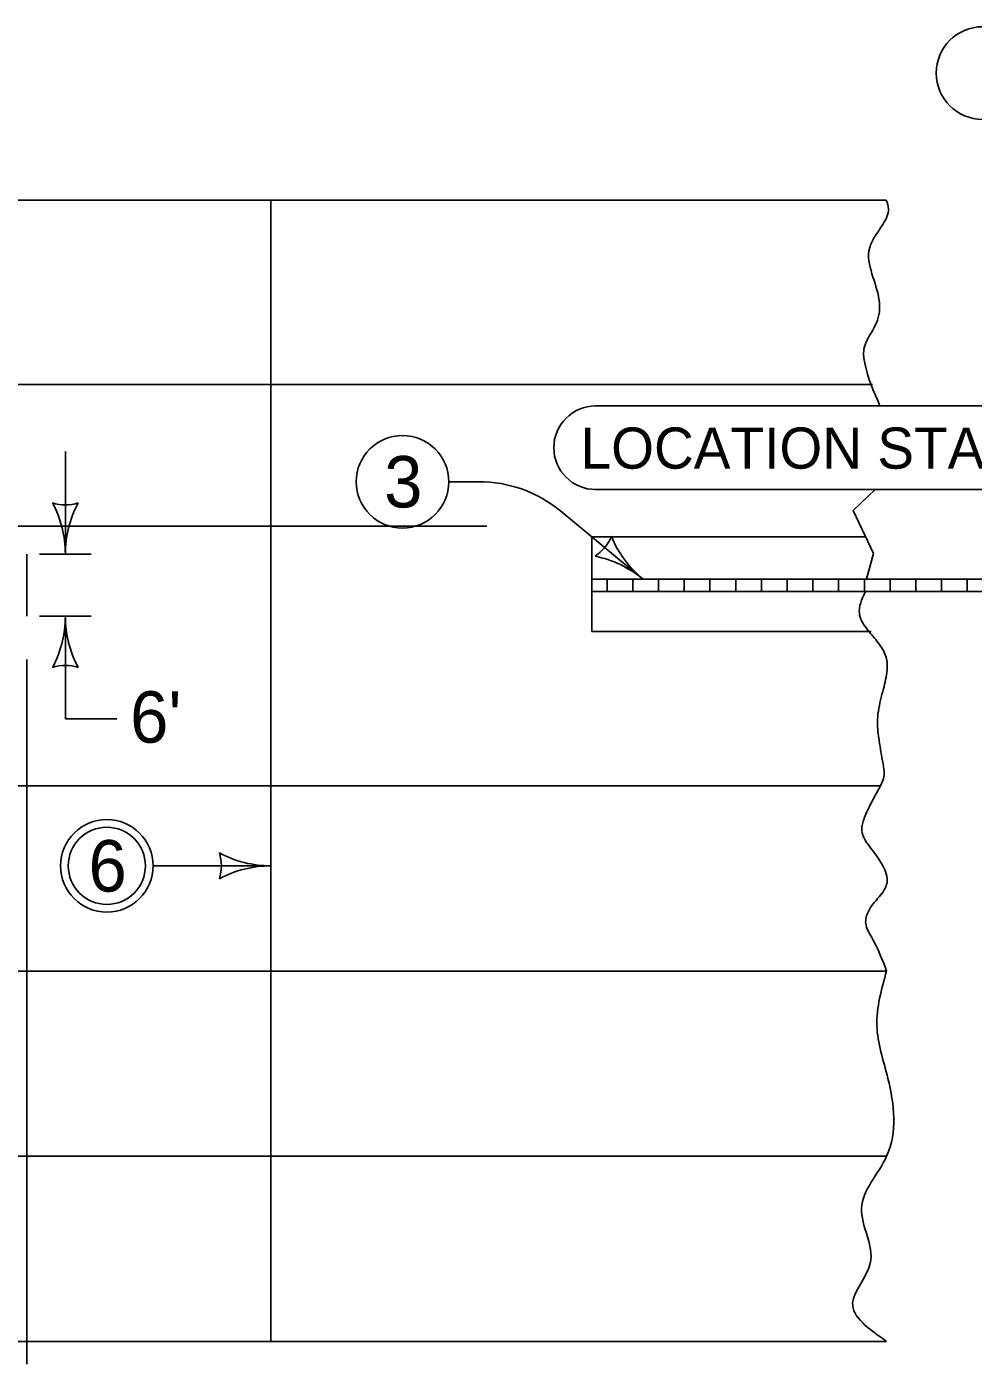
# Model space of a CAD drawing. Extents: x -2135039 to -2131695, y -2139150 to -2136566.
# Drawn here: x -2133246 to -2132878, y -2138511 to -2137991 of the extents above; entities that cross this region are included whole.
import ezdxf

# ---------------------------------------------------------------- set-up
doc = ezdxf.new("R2010")
doc.units = 0
for name, color, linetype in [('dsnStdDimension', 7, 'Continuous'), ('dsnStdLabel', 7, 'Continuous'), ('dsnStdLineDrawingWt4', 7, 'Continuous'), ('dsnStdShading', 7, 'Continuous'), ('Level 10', 7, 'Continuous'), ('Level 2', 7, 'Continuous'), ('Level 3', 7, 'Continuous'), ('Level 7', 7, 'Continuous')]:
    doc.layers.add(name, color=color, linetype=linetype)

msp = doc.modelspace()

# ---------------------------------------------------------------- linework, layer by layer
at = {"layer": 'dsnStdDimension'}
for p, q in [((-2133230.58, -2138196.5), (-2133230.58, -2138156.5)), ((-2133081.57, -2138168.28), (-2133069.91, -2138168.28)), ((-2133038.06, -2138179.74), (-2133006.16, -2138206.1)), ((-2133230.58, -2138260.5), (-2133230.58, -2138220.5)), ((-2133245.58, -2138237.36), (-2133245.58, -2138511.38)), ((-2133230.58, -2138260.5), (-2133210.58, -2138260.5)), ((-2133196.46, -2138317.61), (-2133150.73, -2138317.61))]:
    msp.add_line(p, q, dxfattribs=at)
for centre, radius, start, end in [((-2133069.91, -2138218.28), 50, 50.4322, 90), ((-2133230.58, -2138160.86), 16.42, 252.2666, 287.7333), ((-2133273.08, -2138196.5), 42.5, 0, 28.0725), ((-2133188.08, -2138196.5), 42.5, 151.9275, 180), ((-2133033.63, -2138183.4), 16.42, 302.6988, 338.1655), ((-2132979.09, -2138173.33), 42.5, 202.3597, 230.4322), ((-2133033.23, -2138238.86), 42.5, 50.4322, 78.5047), ((-2133273.08, -2138220.5), 42.5, 331.9275, 0), ((-2133188.08, -2138220.5), 42.5, 180, 208.0725), ((-2133230.58, -2138256.13), 16.42, 72.2666, 107.7334), ((-2133186.37, -2138317.61), 16.42, 342.2666, 17.7333), ((-2133150.73, -2138275.11), 42.5, 241.9275, 270), ((-2133150.73, -2138360.11), 42.5, 90, 118.0725)]:
    msp.add_arc(centre, radius, start, end, dxfattribs=at)
at = {"layer": 'dsnStdLabel'}
for p, q in [((-2132817.04, -2138138.81), (-2133024.52, -2138138.81)), ((-2132817.04, -2138171.31), (-2133024.65, -2138171.31))]:
    msp.add_line(p, q, dxfattribs=at)
msp.add_arc((-2133024.52, -2138155.06), 16.25, 90, 270, dxfattribs=at)
at = {"layer": 'dsnStdLineDrawingWt4'}
for p, q in [((-2134688.01, -2138058.83), (-2133150.73, -2138058.83)), ((-2133150.73, -2138058.83), (-2133150.73, -2138130.5)), ((-2133150.73, -2138058.83), (-2132911.61, -2138058.83)), ((-2133626.99, -2138130.5), (-2132916.93, -2138130.5)), ((-2133150.73, -2138130.5), (-2133150.73, -2138358.5)), ((-2132924.41, -2138179.48), (-2132915.84, -2138171.26)), ((-2132916.57, -2138196.23), (-2132924.41, -2138179.48)), ((-2133025.97, -2138189.71), (-2133025.97, -2138226.5)), ((-2133025.97, -2138189.71), (-2132919.44, -2138189.71)), ((-2133245.58, -2138196.5), (-2133245.58, -2138208.5)), ((-2133240.58, -2138196.5), (-2133220.58, -2138196.5)), ((-2132916.57, -2138196.21), (-2132919.29, -2138206.1)), ((-2133245.58, -2138220.5), (-2133245.58, -2138208.5)), ((-2133025.8, -2138206.1), (-2132697.81, -2138206.1)), ((-2133020.1, -2138210.9), (-2133020.1, -2138206.1)), ((-2133010.1, -2138210.9), (-2133010.1, -2138206.1)), ((-2133000.1, -2138210.9), (-2133000.1, -2138206.1)), ((-2132990.1, -2138210.9), (-2132990.1, -2138206.1)), ((-2132980.1, -2138210.9), (-2132980.1, -2138206.1)), ((-2132970.1, -2138210.9), (-2132970.1, -2138206.1)), ((-2132960.1, -2138210.9), (-2132960.1, -2138206.1)), ((-2132950.1, -2138210.9), (-2132950.1, -2138206.1)), ((-2132940.1, -2138210.9), (-2132940.1, -2138206.1)), ((-2132930.1, -2138210.9), (-2132930.1, -2138206.1)), ((-2132920.1, -2138210.9), (-2132920.1, -2138206.1)), ((-2132910.1, -2138210.9), (-2132910.1, -2138206.1)), ((-2132900.1, -2138210.9), (-2132900.1, -2138206.1)), ((-2132890.1, -2138210.9), (-2132890.1, -2138206.1)), ((-2132880.1, -2138210.9), (-2132880.1, -2138206.1)), ((-2133025.8, -2138210.9), (-2132699.53, -2138210.9)), ((-2133240.58, -2138220.5), (-2133220.58, -2138220.5)), ((-2133025.97, -2138226.5), (-2132917.42, -2138226.5)), ((-2133626.99, -2138286.5), (-2132913.93, -2138286.5)), ((-2134688.98, -2138358.5), (-2133150.73, -2138358.5)), ((-2133150.73, -2138358.5), (-2133150.73, -2138502.5)), ((-2133150.73, -2138358.5), (-2132911.43, -2138358.5)), ((-2134750.5, -2138502.5), (-2132911.43, -2138502.5))]:
    msp.add_line(p, q, dxfattribs=at)
for points in [[(-2132914.03, -2138138.76), (-2132919.94, -2138122.2), (-2132920.28, -2138116.92), (-2132917.92, -2138111.21), (-2132914.44, -2138103.44), (-2132914.25, -2138098.58), (-2132916.74, -2138088.73), (-2132918.31, -2138078.63), (-2132912.93, -2138068.22), (-2132910.7, -2138062.24), (-2132911.61, -2138058.83)], [(-2132911.43, -2138358.5), (-2132917.23, -2138345.45), (-2132919.56, -2138339.99), (-2132918.54, -2138335.31), (-2132914.37, -2138329.68), (-2132911.27, -2138324.04), (-2132912.91, -2138317.6), (-2132917.35, -2138311.07), (-2132921.11, -2138303.77), (-2132920.14, -2138299.02), (-2132914.6, -2138287.94), (-2132912.42, -2138282.19), (-2132912.83, -2138277.9), (-2132914.35, -2138268.88), (-2132914.98, -2138261.83), (-2132914.66, -2138257.54), (-2132912.68, -2138248.78), (-2132911.29, -2138241.52), (-2132911.43, -2138237.17), (-2132913.81, -2138232.16), (-2132917.66, -2138227.23), (-2132921.46, -2138221.65), (-2132922.08, -2138218.44), (-2132921.16, -2138214.35), (-2132919.59, -2138210.9)], [(-2132911.44, -2138358.48), (-2132915.23, -2138379.71), (-2132910.95, -2138400.25), (-2132911.43, -2138430.5), (-2132921.22, -2138450.76), (-2132917.8, -2138472.17), (-2132924.65, -2138487.58), (-2132911.43, -2138502.5)]]:
    msp.add_spline(points, degree=3, dxfattribs=at)
at = {"layer": 'dsnStdShading'}
for p, q in [((-2133150.73, -2138058.83), (-2134688.01, -2138058.83)), ((-2132911.61, -2138058.83), (-2133150.73, -2138058.83)), ((-2133024.52, -2138138.81), (-2132914.03, -2138138.81)), ((-2132915.89, -2138171.31), (-2133024.52, -2138171.31)), ((-2132924.41, -2138179.48), (-2132915.89, -2138171.31)), ((-2132916.57, -2138196.21), (-2132924.41, -2138179.48)), ((-2133020.1, -2138210.9), (-2133020.1, -2138206.1)), ((-2134688.98, -2138358.5), (-2133150.73, -2138358.5)), ((-2133150.73, -2138358.5), (-2132911.43, -2138358.5))]:
    msp.add_line(p, q, dxfattribs=at)
for points in [[(-2132914.03, -2138138.81), (-2132914.03, -2138138.76)], [(-2133020.1, -2138206.1), (-2133010.1, -2138206.1), (-2133000.1, -2138206.1), (-2132990.1, -2138206.1), (-2132980.1, -2138206.1), (-2132970.1, -2138206.1), (-2132960.1, -2138206.1), (-2132950.1, -2138206.1), (-2132940.1, -2138206.1), (-2132930.1, -2138206.1), (-2132920.1, -2138206.1), (-2132919.29, -2138206.1)], [(-2132919.29, -2138206.1), (-2132919.29, -2138206.1)], [(-2132919.59, -2138210.9), (-2132920.1, -2138210.9), (-2132930.1, -2138210.9), (-2132940.1, -2138210.9), (-2132950.1, -2138210.9), (-2132960.1, -2138210.9), (-2132970.1, -2138210.9), (-2132980.1, -2138210.9), (-2132990.1, -2138210.9), (-2133000.1, -2138210.9), (-2133010.1, -2138210.9), (-2133020.1, -2138210.9)]]:
    msp.add_lwpolyline(points, dxfattribs=at)
msp.add_arc((-2133024.52, -2138155.06), 16.25, 90, 270, dxfattribs=at)
for points in [[(-2132914.03, -2138138.76), (-2132919.94, -2138122.2), (-2132920.28, -2138116.92), (-2132917.92, -2138111.21), (-2132914.44, -2138103.44), (-2132914.25, -2138098.58), (-2132916.74, -2138088.73), (-2132918.31, -2138078.63), (-2132912.93, -2138068.22), (-2132910.7, -2138062.24), (-2132911.61, -2138058.83)], [(-2132911.43, -2138358.5), (-2132917.23, -2138345.45), (-2132919.56, -2138339.99), (-2132918.54, -2138335.31), (-2132914.37, -2138329.68), (-2132911.27, -2138324.04), (-2132912.91, -2138317.6), (-2132917.35, -2138311.07), (-2132921.11, -2138303.77), (-2132920.14, -2138299.02), (-2132914.6, -2138287.94), (-2132912.42, -2138282.19), (-2132912.83, -2138277.9), (-2132914.35, -2138268.88), (-2132914.98, -2138261.83), (-2132914.66, -2138257.54), (-2132912.68, -2138248.78), (-2132911.29, -2138241.52), (-2132911.43, -2138237.17), (-2132913.81, -2138232.16), (-2132917.66, -2138227.23), (-2132921.46, -2138221.65), (-2132922.08, -2138218.44), (-2132921.16, -2138214.35), (-2132919.59, -2138210.9)]]:
    msp.add_spline(points, degree=3, dxfattribs=at)
msp.add_open_spline([(-2132919.29, -2138206.1), (-2132918.38, -2138202.8), (-2132917.48, -2138199.51), (-2132916.57, -2138196.21)], degree=2, dxfattribs=at)
at = {"layer": 'Level 10'}
for centre in [(-2132874.15, -2138009.39), (-2133099.57, -2138168.28), (-2133214.46, -2138317.61)]:
    msp.add_circle(centre, 18, dxfattribs=at)
at = {"layer": 'Level 2'}
msp.add_line((-2133457.76, -2138185.58), (-2133066.86, -2138185.58), dxfattribs=at)
msp.add_circle((-2133214.46, -2138317.61), 15, dxfattribs=at)
at = {"layer": 'Level 3'}
msp.add_line((-2133838.08, -2138430.5), (-2132911.43, -2138430.5), dxfattribs=at)

# ---------------------------------------------------------------- texts
at = {"layer": 'dsnStdLabel'}
msp.add_text('LOCATION STATION', height=16, dxfattribs=at).set_placement((-2133030.38, -2138163.2))
at = {"layer": 'Level 7'}
for s, p in [('3', (-2133106.7, -2138178.28)), ("6'", (-2133205.42, -2138269.73)), ('6', (-2133221.59, -2138327.61))]:
    msp.add_text(s, height=20, dxfattribs=at).set_placement(p)

doc.saveas('drawing.dxf')
